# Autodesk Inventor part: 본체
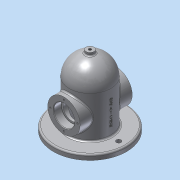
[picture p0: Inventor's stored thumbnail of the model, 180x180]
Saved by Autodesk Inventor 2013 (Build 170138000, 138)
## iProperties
Created: 2019-11
Part Number: 본체
Material: 알루미늄 6061
Document SubType Name: Modeling
Designer: Administrator
Density: 2.71 g/cm^3
Mass: 1110.22 g
Surface Area: 883.25 cm^2
Volume: 409.674 cm^3
Author: Administrator
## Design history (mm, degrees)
sketch "스케치1"
  geometry: C1 r 70 at (0, 0); 1 further point
  constraints: 1 centre point, 1 coincident
  dimensions: "d0" = 140 diameter of C1
extrude "돌출1" new body sketch "스케치1" distance "d1" = 10; taper "d2" = 0 deg
sketch "스케치2"
  geometry: C1 r 70 at (0, 0) reference; C2 r 40 at (0, 0)
  constraints: 1 centre point, 1 coincident
  dimensions: "d3" = 80 diameter of C2
extrude "돌출2" join sketch "스케치2" distance "d4" = 120; taper "d5" = 0 deg
node "작업 평면1"
sketch "스케치3"
  geometry: C1 r 31 at (0, 50); 1 further point
  constraints: 1 centre point, 1 vertical alignment
  dimensions: "d7" = 62 diameter of C1; "d9" = 50 distance of point (0, 0) C1.centre
extrude "돌출3" join sketch "스케치3" stored distance "d10" = 80; taper "d11" = 0 deg
sketch "스케치4"
  geometry: L1 (-50, 81)-(-50, 19) reference; L2 (-50, 50)-(-35, 50); L3 (-35, 50)-(-35, 70); L4 (-35, 70)-(-50, 70); L5 (-50, 70)-(-50, 50); 1 further point
  constraints: 8 end point, 2 parallel, 1 horizontal, 1 midpoint, 1 perpendicular
  dimensions: "d12" = 15 distance of L3.end L4.end; "d14" = 40 diameter of L4 L2
revolve "회전1" sketch "스케치4" stored, may be unused: angle "d15" = 90 deg
sketch "스케치5"
  geometry: C1 r 20 at (0, 0) reference; C2 r 16.5 at (0, 0); 1 further point
  constraints: 1 centre point, 1 coincident
  dimensions: "d16" = 33 diameter of C2
extrude "돌출4" cut sketch "스케치5" stored distance "d17" = 80; taper "d18" = 0 deg
chamfer "모따기1" distance "d19" = 1; stored, may be unused: second distance "d20" = 2, angle "d21" = 45 deg
chamfer "모따기2" distance "d22" = 1; stored, may be unused: second distance "d23" = 2, angle "d24" = 45 deg
fillet "모깎기1" dims "d25" = 40
node "작업 평면2"
sketch "스케치6"
  geometry: C1 r 7.5 at (0, 0); 1 further point
  constraints: 1 centre point, 1 coincident
  dimensions: "d27" = 15 diameter of C1
extrude "돌출5" join sketch "스케치6" stored distance "d28" = 80; taper "d29" = 0 deg
sketch "스케치7"
  geometry: L1 (0, 0)-(-30, 0); L2 (-30, 0)-(-30, 90); L3 (0, 120)-(0, 120); L4 (0, 120)-(0, 0); A1 r 30 centre (0, 90) between (0, 120) and (-30, 90); 2 further points
  constraints: 8 end point, 2 coincident, 2 parallel, 2 point on circle, 2 point on line, 2 tangent, 1 centre point, 1 horizontal, 1 perpendicular
  dimensions: "d31" = 60 diameter of L2 L4; "d35" = 120 distance of L1.end point (-30, 120); "d36" = 30 radius of A1
revolve "회전2" sketch "스케치7" stored, may be unused: angle "d37" = 90 deg
sketch "스케치8"
  geometry: C1 r 7.5 at (0, 0) reference; 1 further point
  constraints: 1 coincident
hole "구멍1" sketch "스케치8" at (0, 0) diameter "d38" = 5.188; stored, may be unused: countersink angle "d42" = 90 deg, drill point angle "d44" = 0 deg; dims "d39" = 6, "d40" = 4, "d41" = 2, "d43" = 8
sketch "스케치9"
  geometry: C1 r 30 at (0, 0) reference; A1 r 55 centre (0, 0) between (-55, 0) and (55, 0)
  constraints: 2 coincident, 2 point on circle, 1 centre point
  dimensions: "d45" = 110 diameter of A1
hole "구멍2" sketch "스케치9" at (-55, 0), (55, 0) diameter "d46" = 9; stored, may be unused: countersink angle "d50" = 90 deg, drill point angle "d52" = 0 deg; dims "d47" = 6, "d48" = 4, "d49" = 2, "d51" = 10
fillet "모깎기2" dims "d53" = 3
fillet "모깎기3" dims "d54" = 3
fillet "모깎기4" dims "d55" = 3
fillet "모깎기5" dims "d56" = 3
sketch "스케치10" dims "d57" = 52
  geometry: C1 r 31 at (0, 0) reference; 3 further points
  constraints: 2 coincident, 1 vertical alignment, 2 other
hole "구멍3" sketch "스케치10" at (0, 26) diameter "d58" = 3.242; stored, may be unused: countersink angle "d62" = 90 deg, drill point angle "d64" = 118 deg; dims "d59" = 8, "d60" = 4, "d61" = 2, "d63" = 10
node "작업 평면3"
sketch "스케치11"
  geometry: L1 (-70, 0)-(70, 0) reference; 3 further points
  constraints: 1 midpoint, 1 vertical alignment, 1 other
  dimensions: "d69" = 50 distance from line of L1 point (0, 50)
feature "엠보싱1" sketch "스케치11" dims "d1" = 10, "d12" = 15, "d14" = 40, "d70" = 0.5, "d71" = 0
fillet "모깎기6" dims "d72" = 0.3
node "솔리드1"
mirror "대칭1"
mirror "대칭2"
pattern_circular "원형 패턴1" dims angle "d66" = 360 deg
mirror "대칭3"
other parameters: "d26" = 135
